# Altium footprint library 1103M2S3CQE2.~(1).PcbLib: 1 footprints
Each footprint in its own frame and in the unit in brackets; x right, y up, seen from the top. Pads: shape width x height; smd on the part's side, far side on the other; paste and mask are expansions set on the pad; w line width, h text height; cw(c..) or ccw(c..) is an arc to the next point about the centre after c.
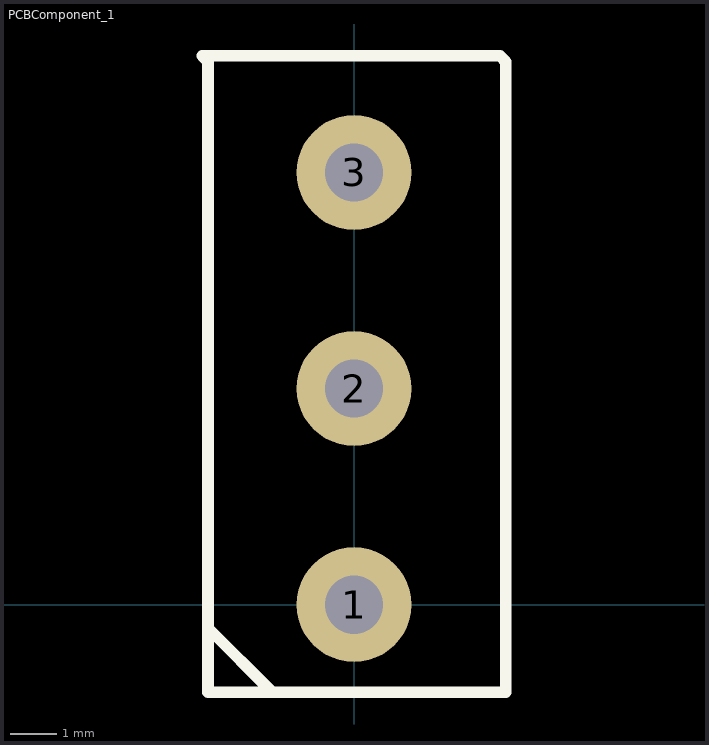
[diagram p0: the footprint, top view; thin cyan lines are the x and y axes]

## PCBComponent_1 [mm]
pads (3):
  round 2.5 hole 1.27 square: 1(0,0) 2(0,4.7) 3(0,9.4)
Top Overlay:
  lines w0.254: -3.175,-0.381 -3.175,-0.508 -1.778,-1.905 ; -3.302,11.938 -3.175,11.811 -3.175,-1.905 3.302,-1.905 3.302,11.811 3.175,11.938 -3.302,11.938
